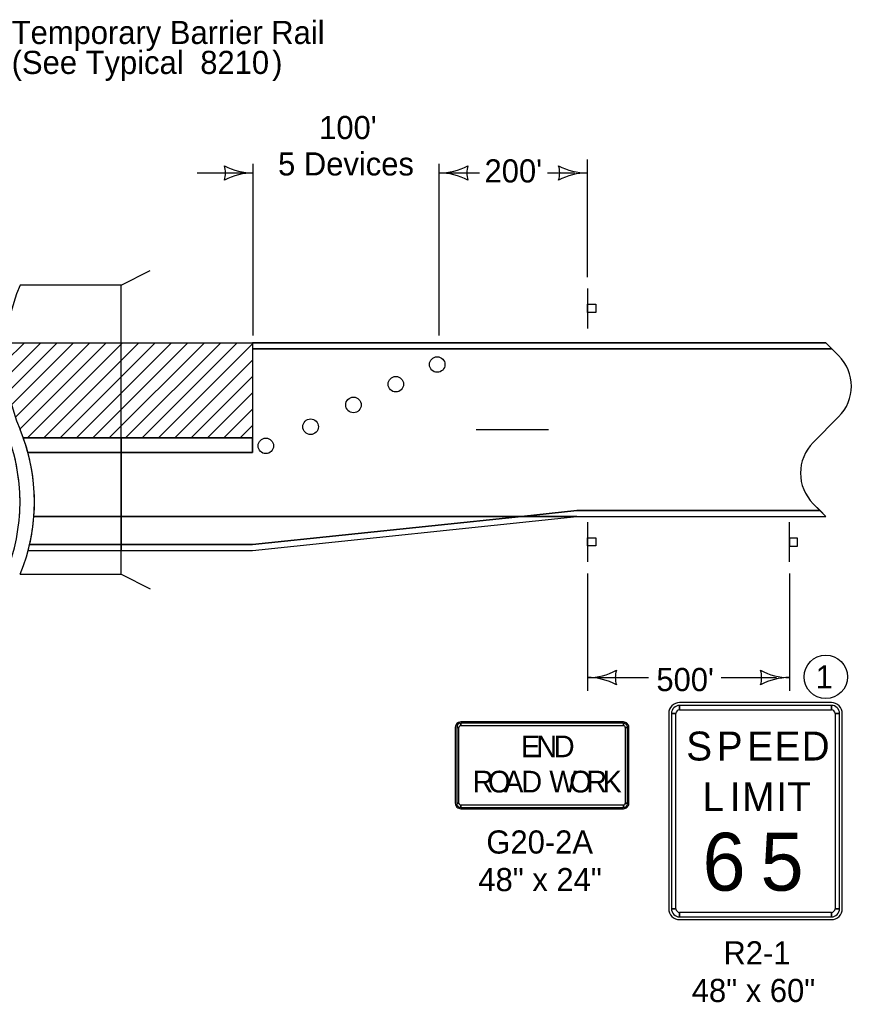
# Model space of a CAD drawing. Extents: x 10134 to 13311, y 7934 to 9733.
# Drawn here: x 12689 to 13264, y 8907 to 9587 of the extents above; entities that cross this region are included whole.
import ezdxf

# ---------------------------------------------------------------- set-up
doc = ezdxf.new("R2010")
doc.units = 0
for name, color, linetype in [('dsnCellElements', 7, 'Continuous'), ('dsnstdModifiedBlock', 7, 'Continuous'), ('dsnStdNote', 7, 'Continuous'), ('dsnStdShading', 7, 'Continuous'), ('SheetText', 7, 'Continuous')]:
    doc.layers.add(name, color=color, linetype=linetype)

msp = doc.modelspace()

# ---------------------------------------------------------------- linework, layer by layer
at = {"layer": 'dsnCellElements'}
for p, q in [((13081.72, 9400.58), (13081.72, 9373.08)), ((12679.39, 9350.06), (12692.36, 9363.04)), ((12680.07, 9339.43), (12703.68, 9363.04)), ((12681.49, 9329.54), (12714.99, 9363.04)), ((12683.55, 9320.28), (12726.31, 9363.04)), ((12686.14, 9311.57), (12737.62, 9363.04)), ((12689.23, 9303.34), (12748.93, 9363.04)), ((12694.51, 9297.31), (12760.25, 9363.04)), ((12705.83, 9297.31), (12771.56, 9363.04)), ((12717.14, 9297.31), (12782.87, 9363.04)), ((12728.45, 9297.31), (12794.19, 9363.04)), ((12739.77, 9297.31), (12805.5, 9363.04)), ((12751.08, 9297.31), (12816.81, 9363.04)), ((12762.39, 9297.31), (12828.13, 9363.04)), ((12773.71, 9297.31), (12839.44, 9363.04)), ((12785.02, 9297.31), (12850.11, 9362.4)), ((12850.11, 9363.04), (12850.11, 9297.31)), ((12796.34, 9297.31), (12850.11, 9351.09)), ((12807.65, 9297.31), (12850.11, 9339.77)), ((12818.96, 9297.31), (12850.11, 9328.46)), ((12830.28, 9297.31), (12850.11, 9317.15)), ((12841.59, 9297.31), (12850.11, 9305.83)), ((12759.35, 9297.31), (12759.35, 9287.31)), ((12850.11, 9287.31), (12850.11, 9297.31)), ((12759.35, 9287.31), (12850.11, 9287.31)), ((12850.11, 9223.54), (13074.31, 9247.04)), ((13074.31, 9247.04), (13242.66, 9247.04)), ((13081.72, 9239.13), (13081.72, 9211.63)), ((13221.36, 9211.63), (13221.36, 9239.13)), ((13250.45, 9114.28), (13145.45, 9114.28)), ((13145.45, 9109.28), (13145.45, 9112.4)), ((13250.45, 9112.4), (13250.45, 9109.28)), ((13137.95, 9106.78), (13137.95, 8971.78)), ((13139.83, 9106.78), (13142.95, 9106.78)), ((13252.95, 9106.78), (13256.08, 9106.78)), ((13257.95, 8971.78), (13257.95, 9106.78)), ((13106.63, 9100.93), (12994.13, 9100.93)), ((12994.13, 9098.43), (12994.13, 9099.99)), ((13106.63, 9099.99), (13106.63, 9098.43)), ((12990.38, 9097.18), (12990.38, 9044.68)), ((12991.32, 9097.18), (12992.88, 9097.18)), ((13107.88, 9097.18), (13109.44, 9097.18)), ((13110.38, 9044.68), (13110.38, 9097.18)), ((12992.88, 9044.68), (12991.32, 9044.68)), ((13109.44, 9044.68), (13107.88, 9044.68)), ((12994.13, 9041.87), (12994.13, 9043.43)), ((12994.13, 9040.93), (13106.63, 9040.93)), ((13106.63, 9043.43), (13106.63, 9041.87)), ((13142.95, 8971.78), (13139.83, 8971.78)), ((13256.08, 8971.78), (13252.95, 8971.78)), ((13145.45, 8966.16), (13145.45, 8969.28)), ((13145.45, 8964.28), (13250.45, 8964.28)), ((13250.45, 8969.28), (13250.45, 8966.16))]:
    msp.add_line(p, q, dxfattribs=at)
for points in [[(13081.82, 9384.13), (13081.82, 9389.76), (13087.44, 9389.76), (13087.44, 9384.13)], [(13081.82, 9222.68), (13081.82, 9228.31), (13087.44, 9228.31), (13087.44, 9222.68)], [(13221.45, 9228.08), (13221.45, 9222.46), (13227.08, 9222.46), (13227.08, 9228.08)], [(13250.45, 9112.4), (13145.45, 9112.4), (13145.45, 9109.28), (13250.45, 9109.28), (13250.45, 9112.4)], [(13139.83, 9106.78), (13139.83, 8971.78), (13142.95, 8971.78), (13142.95, 9106.78), (13139.83, 9106.78)], [(13256.08, 8971.78), (13256.08, 9106.78), (13252.95, 9106.78), (13252.95, 8971.78), (13256.08, 8971.78)], [(13106.63, 9099.99), (12994.13, 9099.99), (12994.13, 9098.43), (13106.63, 9098.43), (13106.63, 9099.99)], [(12991.32, 9097.18), (12991.32, 9044.68), (12992.88, 9044.68), (12992.88, 9097.18), (12991.32, 9097.18)], [(13109.44, 9044.68), (13109.44, 9097.18), (13107.88, 9097.18), (13107.88, 9044.68), (13109.44, 9044.68)], [(12994.13, 9041.87), (13106.63, 9041.87), (13106.63, 9043.43), (12994.13, 9043.43), (12994.13, 9041.87)], [(13145.45, 8966.16), (13250.45, 8966.16), (13250.45, 8969.28), (13145.45, 8969.28), (13145.45, 8966.16)]]:
    msp.add_lwpolyline(points, close=True, dxfattribs=at)
msp.add_lwpolyline([(12850.11, 9297.31), (12841.59, 9297.31), (12830.28, 9297.31), (12818.96, 9297.31), (12807.65, 9297.31), (12796.34, 9297.31), (12785.02, 9297.31), (12773.71, 9297.31), (12762.39, 9297.31), (12759.35, 9297.31)], dxfattribs=at)
for centre in [(12977.84, 9348.08), (12977.84, 9348.08), (12949.24, 9334.47), (12949.24, 9334.47), (12919.92, 9320.16), (12919.92, 9320.16), (12890.29, 9305.06), (12890.29, 9305.06), (12859.34, 9291.84), (12859.34, 9291.84)]:
    msp.add_circle(centre, 5.37, dxfattribs=at)
for centre, radius, start, end in [((13145.45, 9106.78), 7.5, 90.00021, 179.99985), ((13145.45, 9106.78), 5.62, 90.00021, 179.99985), ((13250.45, 9106.78), 7.5, 0, 90.00021), ((13250.45, 9106.78), 5.62, 0, 90.00021), ((13145.45, 9106.78), 2.5, 90.00021, 179.99985), ((13250.45, 9106.78), 2.5, 0, 90.00021), ((12994.13, 9097.18), 3.75, 90.00021, 179.99985), ((12994.13, 9097.18), 2.81, 90.00021, 179.99985), ((13106.63, 9097.18), 3.75, 0, 90.00021), ((13106.63, 9097.18), 2.81, 0, 90.00021), ((12994.13, 9097.18), 1.25, 90.00021, 179.99985), ((13106.63, 9097.18), 1.25, 0, 90.00021), ((12994.13, 9044.68), 3.75, 179.99985, 270.00006), ((12994.13, 9044.68), 2.81, 179.99985, 270.00006), ((12994.13, 9044.68), 1.25, 179.99985, 270.00006), ((13106.63, 9044.68), 3.75, 270.00006, 0.00027), ((13106.63, 9044.68), 2.81, 270.00006, 0.00027), ((13106.63, 9044.68), 1.25, 270.00006, 0.00027), ((13145.45, 8971.78), 7.5, 179.99985, 270.00006), ((13145.45, 8971.78), 5.62, 179.99985, 270.00006), ((13145.45, 8971.78), 2.5, 179.99985, 270.00006), ((13250.45, 8971.78), 7.5, 270.00006, 0.00027), ((13250.45, 8971.78), 5.62, 270.00006, 0.00027), ((13250.45, 8971.78), 2.5, 270.00006, 0.00027)]:
    msp.add_arc(centre, radius, start, end, dxfattribs=at)
at = {"layer": 'dsnstdModifiedBlock'}
for p, q in [((12759.35, 9403.04), (12779.35, 9413.04)), ((13255.45, 9354.25), (13246.66, 9363.04)), ((13237.88, 9294.26), (13255.45, 9311.83)), ((12691.58, 9297.31), (12850.11, 9297.31)), ((12850.11, 9297.31), (12850.11, 9287.31)), ((12850.11, 9287.31), (12694.75, 9287.31)), ((13246.66, 9243.04), (13237.88, 9251.83)), ((12698.97, 9243.04), (13074.33, 9243.04)), ((12850.11, 9223.54), (13074.31, 9247.04)), ((12695.96, 9223.54), (12850.11, 9223.54)), ((12689.35, 9203.04), (12759.35, 9203.04)), ((12759.35, 9203.04), (12779.35, 9193.04))]:
    msp.add_line(p, q, dxfattribs=at)
for points in [[(12759.35, 9203.04), (12759.35, 9403.04), (12689.35, 9403.04)], [(12850.11, 9359.04), (13250.66, 9359.04)], [(13004.77, 9303.04), (13054.77, 9303.04)], [(13004.77, 9303.04), (13054.77, 9303.04)], [(12691.58, 9297.31), (12704.65, 9297.31)], [(12707.82, 9287.31), (12694.75, 9287.31)], [(13074.31, 9247.04), (13242.66, 9247.04)]]:
    msp.add_lwpolyline(points, dxfattribs=at)
for centre, radius, start, end in [((12809.35, 9353.04), 130, 157.38014, 202.61987), ((13234.24, 9333.04), 30, 315.00015, 44.99873), ((12559.35, 9253.04), 130, 337.38014, 22.61987), ((12569.35, 9253.04), 130, 337.38014, 22.61987), ((13259.09, 9273.04), 30, 135, 225)]:
    msp.add_arc(centre, radius, start, end, dxfattribs=at)
at = {"layer": 'dsnStdNote'}
msp.add_circle((13246.54, 9132.08), 15, dxfattribs=at)
at = {"layer": 'dsnStdShading'}
for p, q in [((12679.74, 9363.04), (13246.66, 9363.04)), ((13246.66, 9363.04), (12850.11, 9363.04)), ((12850.11, 9363.04), (12850.11, 9359.04)), ((12850.11, 9359.04), (13250.66, 9359.04)), ((13250.66, 9359.04), (12850.11, 9359.04)), ((12850.11, 9359.04), (12850.11, 9351.09)), ((13250.66, 9359.04), (13246.66, 9363.04)), ((13255.45, 9354.26), (13250.66, 9359.04)), ((12850.11, 9351.09), (12850.11, 9339.77)), ((12850.11, 9339.77), (12850.11, 9328.46)), ((13237.88, 9294.26), (13255.45, 9311.83)), ((12759.35, 9287.31), (12759.35, 9297.31)), ((12850.11, 9297.31), (12850.11, 9287.31)), ((12694.75, 9287.31), (12707.82, 9287.31)), ((12707.82, 9287.31), (12759.35, 9287.31)), ((12759.35, 9243.04), (12759.35, 9287.31)), ((12850.11, 9287.31), (12759.35, 9287.31)), ((12759.35, 9287.31), (12759.35, 9243.04)), ((13242.66, 9247.04), (13237.88, 9251.83)), ((12759.35, 9243.04), (12698.97, 9243.04)), ((12698.97, 9243.04), (12759.35, 9243.04)), ((12992.5, 9243.04), (12759.35, 9243.04)), ((12759.35, 9243.04), (12759.35, 9223.54)), ((12759.35, 9223.54), (12759.35, 9243.04)), ((12759.35, 9243.04), (13036.17, 9243.04)), ((12850.11, 9219.54), (13074.31, 9243.04)), ((12850.11, 9223.54), (13036.16, 9243.04)), ((12850.11, 9219.54), (13074.31, 9243.04)), ((13036.16, 9243.04), (12850.11, 9223.54)), ((12992.5, 9243.04), (13246.66, 9243.04)), ((13036.16, 9243.04), (12992.5, 9243.04)), ((13074.31, 9247.04), (13036.16, 9243.04)), ((13074.31, 9243.04), (13036.16, 9243.04)), ((13036.16, 9243.04), (13246.66, 9243.04)), ((13036.17, 9243.04), (13074.31, 9247.04)), ((13242.66, 9247.04), (13074.31, 9247.04)), ((13074.31, 9247.04), (13242.66, 9247.04)), ((13246.66, 9243.04), (13242.66, 9247.04)), ((12695.96, 9223.54), (12709.02, 9223.54)), ((12709.02, 9223.54), (12695.96, 9223.54)), ((12709.02, 9223.54), (12759.35, 9223.54)), ((12759.35, 9223.54), (12709.02, 9223.54)), ((12759.35, 9223.54), (12850.11, 9223.54)), ((12850.11, 9223.54), (12759.35, 9223.54)), ((12759.35, 9223.54), (12759.35, 9219.54)), ((12759.35, 9219.54), (12759.35, 9223.54)), ((12694.96, 9219.54), (12759.35, 9219.54)), ((12694.96, 9219.54), (12850.11, 9219.54)), ((12694.96, 9219.54), (12708.02, 9219.54)), ((12759.35, 9219.54), (12850.11, 9219.54))]:
    msp.add_line(p, q, dxfattribs=at)
for points in [[(13250.66, 9359.04), (13250.66, 9359.04)], [(13250.66, 9359.04), (13250.66, 9359.04)], [(12850.11, 9328.46), (12850.11, 9317.15), (12850.11, 9305.83), (12850.11, 9297.31)], [(12759.35, 9297.31), (12751.08, 9297.31), (12739.77, 9297.31), (12728.45, 9297.31), (12717.14, 9297.31), (12705.83, 9297.31), (12704.65, 9297.31), (12694.51, 9297.31), (12691.58, 9297.31)], [(12759.35, 9287.31), (12707.82, 9287.31), (12694.75, 9287.31)], [(12992.5, 9243.04), (12992.5, 9243.04)], [(13242.66, 9247.04), (13242.66, 9247.04)], [(13242.66, 9247.04), (13242.66, 9247.04)]]:
    msp.add_lwpolyline(points, dxfattribs=at)
for centre, radius, start, end in [((13234.24, 9333.04), 30, 315, 45), ((12569.35, 9253.04), 130, 15.28322, 19.90817), ((13259.09, 9273.04), 30, 135, 225), ((12559.35, 9253.04), 130, 355.58827, 15.28231), ((12569.35, 9253.04), 130, 355.58916, 15.28322), ((12569.35, 9253.04), 130, 346.88255, 355.58916), ((12569.35, 9253.04), 130, 345.06535, 346.88255)]:
    msp.add_arc(centre, radius, start, end, dxfattribs=at)
at = {"layer": 'SheetText'}
for p, q in [((12850.64, 9368.09), (12850.64, 9486.8)), ((12979.14, 9368.09), (12979.14, 9486.8)), ((13081.72, 9408.58), (13081.72, 9489.79)), ((12811.86, 9480.57), (12850.7, 9480.57)), ((12979.14, 9480.57), (13007.07, 9480.57)), ((13054.15, 9480.57), (13072.86, 9480.57)), ((13081.72, 9203.63), (13081.72, 9122.43)), ((13221.36, 9203.63), (13221.36, 9122.43)), ((13081.85, 9131.64), (13123.88, 9131.64)), ((13174.31, 9131.64), (13212.5, 9131.64))]:
    msp.add_line(p, q, dxfattribs=at)
for centre, radius, start, end in [((12815.07, 9480.57), 16.42, 342.26665, 17.73335), ((12850.7, 9523.07), 42.5, 241.92751, 270), ((12850.7, 9438.07), 42.5, 90, 118.07249), ((12979.08, 9523.07), 42.5, 270, 298.07249), ((12979.08, 9438.07), 42.5, 61.92751, 90), ((13014.71, 9480.57), 16.42, 162.26665, 197.73335), ((13046.16, 9480.57), 16.42, 342.26665, 17.73335), ((13081.79, 9523.07), 42.5, 241.92751, 270), ((13081.79, 9438.07), 42.5, 90, 118.07249), ((13081.79, 9174.14), 42.5, 270, 298.07249), ((13117.43, 9131.64), 16.42, 162.26665, 197.73335), ((13185.79, 9131.64), 16.42, 342.26665, 17.73335), ((13221.43, 9174.14), 42.5, 241.92751, 270), ((13081.79, 9089.15), 42.5, 61.92751, 90), ((13221.43, 9089.14), 42.5, 90, 118.07249)]:
    msp.add_arc(centre, radius, start, end, dxfattribs=at)

# ---------------------------------------------------------------- texts
at = {"layer": 'dsnCellElements'}
for s, height, p in [('S', 20, (13150.08, 9074.28)), ('P', 20, (13171.18, 9074.28)), ('E', 20, (13192.27, 9074.28)), ('E', 20, (13211.08, 9074.28)), ('D', 20, (13229.89, 9074.28)), ('E', 15, (13035.71, 9076.55)), ('N', 15, (13046.32, 9076.55)), ('D', 15, (13058.41, 9076.55)), ('R', 15, (13002.24, 9052.18)), ('O', 15, (13012.93, 9052.18)), ('A', 15, (13024.08, 9052.18)), ('D', 15, (13035.94, 9052.18)), ('W', 15, (13055.39, 9052.18)), ('O', 15, (13069.12, 9052.18)), ('R', 15, (13080.89, 9052.18)), ('K', 15, (13092.19, 9052.18)), ('L', 20, (13161.33, 9039.28)), ('I', 20, (13180.14, 9039.28)), ('M', 20, (13188.74, 9039.28)), ('I', 20, (13212.33, 9039.28)), ('T', 20, (13219.89, 9039.28)), ('6', 40, (13161.33, 8984.28)), ('5', 40, (13201.45, 8984.28))]:
    msp.add_text(s, height=height, dxfattribs=at).set_placement(p)
at = {"layer": 'dsnStdNote'}
msp.add_text('1', height=16, dxfattribs=at).set_placement((13239.55, 9124.08))
at = {"layer": 'SheetText'}
for s, p in [('Temporary Barrier Rail', (12683.58, 9569.7)), ('(See Typical ', (12683.58, 9548.99)), ('8210', (12814.01, 9548.99)), (')', (12863.72, 9548.99)), ("100'", (12896.2, 9503.96)), ('5 Devices', (12867.8, 9478.81)), ("200'", (13010.57, 9473.97)), ("500'", (13129.41, 9122.25)), ('G20-2A', (13011.85, 9009.93)), ('48" x 24"', (13006.31, 8983.93)), ('R2-1', (13175.79, 8933.28)), ('48" x 60"', (13153.89, 8907.28))]:
    msp.add_text(s, height=16, dxfattribs=at).set_placement(p)

doc.saveas('drawing.dxf')
